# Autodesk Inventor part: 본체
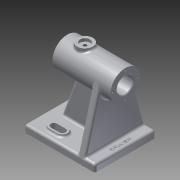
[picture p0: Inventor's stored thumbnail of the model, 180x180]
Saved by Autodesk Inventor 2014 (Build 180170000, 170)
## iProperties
Created: 2019-10
Part Number: 본체
Material: Aluminum 6061
Document SubType Name: Modeling
Designer: kh
Density: 2.71 g/cm^3
Appearance: Aluminum - Flat
Mass: 588.616 g
Surface Area: 540.304 cm^2
Volume: 217.201 cm^3
Author: kh
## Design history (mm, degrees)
sketch "Sketch1"
  geometry: L1 (-50, -43)-(50, -43); L2 (50, -43)-(50, 43); L3 (50, 43)-(-50, 43); L4 (-50, 43)-(-50, -43); L5 (-50, -43)-(50, 43); L6 (50, -43)-(-50, 43); L7 (-24, 27)-(-12, 27); L8 (-24, 31.5)-(-12, 31.5); L9 (-12, 22.5)-(-24, 22.5); L10 (-24, -27)-(-12, -27); L11 (-24, -22.5)-(-12, -22.5); L12 (-12, -31.5)-(-24, -31.5); A1 r 4.5 centre (-24, 27) between (-24, 31.5) and (-24, 22.5); A2 r 4.5 centre (-12, 27) between (-12, 22.5) and (-12, 31.5); A3 r 4.5 centre (-24, -27) between (-24, -22.5) and (-24, -31.5); A4 r 4.5 centre (-12, -27) between (-12, -31.5) and (-12, -22.5); 3 further points
  constraints: 28 end point, 8 point on circle, 8 tangent, 6 parallel, 4 centre point, 4 midpoint, 1 horizontal, 1 perpendicular
  dimensions: "d0" = 100 distance of L3.end L2.end; "d1" = 86 distance of L2.end L1.end; "d2" = 27 distance from line of L7 point (0, 0); "d3" = 12 distance of L8.start L8.end; "d4" = 26 distance from line of L4 L8.start; "d5" = 9 distance between parallel lines of L9 L8; "d6" = 12 distance of L11.start L11.end; "d7" = 9 distance between parallel lines of L12 L11; "d9" = 26 distance from line of L4 L11.start; "d80" = 27 vertical distance of point (-18, -27) point (0, 0)
extrude "Extrusion1" new body sketch "Sketch1" distance "d10" = 10; taper "d11" = 0 deg
sketch "Sketch2"
  geometry: L1 (-24, 27)-(-12, 27); L2 (-24, 20)-(-12, 20); L3 (-12, 34)-(-24, 34); L4 (-24, -27)-(-12, -27); L5 (-24, -34)-(-12, -34); L6 (-12, -20)-(-24, -20); L7 (-24, 27)-(-12, 27); L8 (-24, 22.5)-(-12, 22.5); L9 (-12, 31.5)-(-24, 31.5); L10 (-24, -27)-(-12, -27); L11 (-24, -31.5)-(-12, -31.5); L12 (-12, -22.5)-(-24, -22.5); A1 r 4.5 centre (-24, 27) between (-24, 31.5) and (-24, 22.5) reference; A2 r 4.5 centre (-12, 27) between (-12, 22.5) and (-12, 31.5) reference; A3 r 4.5 centre (-24, -27) between (-24, -22.5) and (-24, -31.5) reference; A4 r 4.5 centre (-12, -27) between (-12, -31.5) and (-12, -22.5) reference; A5 r 7 centre (-24, 27) between (-24, 34) and (-24, 20); A6 r 7 centre (-12, 27) between (-12, 20) and (-12, 34); A7 r 7 centre (-24, -27) between (-24, -20) and (-24, -34); A8 r 7 centre (-12, -27) between (-12, -34) and (-12, -20); A9 r 4.5 centre (-24, 27) between (-24, 31.5) and (-24, 22.5); A10 r 4.5 centre (-12, 27) between (-12, 22.5) and (-12, 31.5); A11 r 4.5 centre (-24, -27) between (-24, -22.5) and (-24, -31.5); A12 r 4.5 centre (-12, -27) between (-12, -31.5) and (-12, -22.5); 5 further points
  constraints: 32 end point, 16 point on circle, 16 tangent, 8 centre point, 7 equal length, 4 midpoint, 1 horizontal
  dimensions: "d12" = 14 distance between parallel lines of L2 L3; "d13" = 14 distance between parallel lines of L5 L6; "d14" = 9 distance between parallel lines of L11 L12; "d15" = 9 distance between parallel lines of L9 L8
extrude "Extrusion2" join sketch "Sketch2" distance "d16" = 3; taper "d17" = 0 deg
sketch "Sketch3"
  geometry: L1 (32, 86)-(-30, 86); L2 (-30, 86)-(-30, 100.5); L3 (-30, 100.5)-(32, 100.5); L4 (32, 100.5)-(32, 86); L5 (-30, 86)-(-50, 86); L6 (-50, 86)-(-50, 97.5); L7 (-50, 97.5)-(-30, 97.5); L8 (-30, 97.5)-(-30, 86); L9 (32, 86)-(-50, 86); L10 (-50, 86)-(-50, 107); L11 (-50, 107)-(32, 107); L12 (32, 107)-(32, 86); L13 (-50, 0)-(-50, 10) reference; L14 (50, 0)-(-50, 0) reference; 5 further points
  constraints: 24 end point, 6 parallel, 4 midpoint, 3 horizontal, 3 perpendicular, 2 vertical alignment
  dimensions: "d18" = 29 diameter of L3 L1; "d19" = 23 diameter of L7 L5; "d20" = 42 diameter of L11 L5; "d21" = 82 distance of L10.end L11.end; "d22" = 62 distance of L2.end L3.end; "d23" = 86 distance from line of L1.start L14
revolve "Revolution1" sketch "Sketch3" stored, may be unused: angle "d24" = 90 deg
workplane "Work Plane1"
sketch "Sketch4"
  geometry: L1 (-32, 21)-(-32, -21) reference; C1 r 11 at (-7, 0); 2 further points
  constraints: 1 centre point, 1 coincident, 1 horizontal alignment, 1 midpoint
  dimensions: "d26" = 22 diameter of C1; "d79" = 25 distance from line of point (-7, 0) L1
extrude "Extrusion3" join sketch "Sketch4" stored distance "d27" = 3; taper "d28" = 0 deg
hole "Hole1" diameter "d31" = 4.917; stored, may be unused: countersink angle "d35" = 90 deg, drill point angle "d37" = 118 deg; dims "d29" = 10, "d30" = 10, "d32" = 6, "d33" = 14, "d34" = 4, "d36" = 8
sketch "Sketch6" dims "d39" = 36
  geometry: C1 r 21 at (0, 0) reference; 3 further points
  constraints: 1 coincident, 1 horizontal alignment, 2 other
hole "Hole2" sketch "Sketch6" at (18, 0) diameter "d40" = 2.459; stored, may be unused: countersink angle "d44" = 90 deg, drill point angle "d46" = 118 deg; dims "d41" = 8, "d42" = 14, "d43" = 4, "d45" = 10
pattern_circular "Circular Pattern1" dims angle "d48" = 360 deg
workplane "Work Plane2"
mirror "Mirror1"
fillet "Fillet1" dims "d50" = 3
fillet "Fillet2" dims "d51" = 3
fillet "Fillet3" dims "d52" = 3
workplane "Work Plane4"
sketch "Sketch8"
  geometry: L1 (-10, 0)-(-10, 80) reference; L2 (-7, 83)-(0, 83) reference; L3 (0, 83)-(0, -3) reference; L4 (0, -3)-(-7, -3) reference; L5 (-7.783, 82.896)-(-91.48, 60.272); L6 (-7.783, -2.896)-(-91.48, 19.728); L7 (-10, 80)-(-10, 0); C1 r 11.5 at (-86, 40) reference; A1 r 3 centre (-7, 80) between (-7, 83) and (-10, 80) reference; A2 r 3 centre (-7, 0) between (-10, 0) and (-7, -3) reference; A3 r 21 centre (-86, 40) between (-91.48, 60.272) and (-91.48, 19.728) reference; A4 r 21 centre (-86, 40) between (-91.48, 19.728) and (-91.48, 60.272); A5 r 3 centre (-7, 0) between (-10, 0) and (-7.783, -2.896); A6 r 3 centre (-7, 80) between (-7.783, 82.896) and (-10, 80); 1 further point
  constraints: 10 point on circle, 8 tangent, 6 end point, 3 centre point, 3 coincident, 1 collinear
extrude "Extrusion4" join sketch "Sketch8" distance "d56" = 10; taper "d57" = 0 deg
sketch "Sketch9"
  geometry: L1 (0, 106)-(4.542, 106) reference; L2 (4.542, 106)-(4.542, 100.5) reference; L3 (4.542, 100.5)-(-30, 100.5) reference; L4 (-30, 100.5)-(-30, 97.5) reference; L5 (-30, 97.5)-(-50, 97.5) reference; L6 (-50, 97.5)-(-50, 102.77) reference; L7 (-50, 102.77)-(-40, 102.77) reference; L8 (-40, 102.77)-(-39.261, 104) reference; L9 (-39.261, 104)-(-40, 105.229) reference; L10 (-40, 105.229)-(-50, 105.229) reference; L11 (-50, 105.229)-(-50, 107) reference; L12 (-50, 107)-(-4, 107) reference; L13 (-4, 107)-(-4, 110) reference; L14 (-4, 110)-(0, 110) reference; L15 (0, 110)-(0, 106) reference; L16 (9.459, 106)-(14, 106) reference; L17 (14, 106)-(14, 110) reference; L18 (14, 110)-(18, 110) reference; L19 (18, 110)-(18, 107) reference; L20 (18, 107)-(32, 107) reference; L21 (32, 107)-(32, 105.23) reference; L22 (32, 105.23)-(22, 105.23) reference; L23 (22, 105.23)-(21.261, 104) reference; L24 (21.261, 104)-(22, 102.771) reference; L25 (22, 102.771)-(32, 102.771) reference; L26 (32, 102.771)-(32, 100.5) reference; L27 (32, 100.5)-(9.459, 100.5) reference; L28 (9.459, 100.5)-(9.459, 106) reference; L29 (-30, 71.5)-(32, 71.5) reference; L30 (32, 71.5)-(32, 69.23) reference; L31 (32, 69.23)-(22, 69.23) reference; L32 (22, 69.23)-(21.261, 68) reference; L33 (21.261, 68)-(22, 66.77) reference; L34 (22, 66.77)-(32, 66.77) reference; L35 (32, 66.77)-(32, 65) reference; L36 (32, 65)-(-25, 65) reference; L37 (-25, 65)-(-25, 10) reference; L38 (-25, 10)-(47, 10) reference; L39 (50, 7)-(50, 0) reference; L40 (50, 0)-(-50, 0) reference; L41 (-50, 0)-(-50, 7) reference; L42 (-47, 10)-(-35, 10) reference; L43 (-35, 10)-(-35, 65) reference; L44 (-35, 65)-(-50, 65) reference; L45 (-50, 65)-(-50, 66.77) reference; L46 (-50, 66.77)-(-40, 66.77) reference; L47 (-40, 66.77)-(-39.261, 68) reference; L48 (-39.261, 68)-(-40, 69.229) reference; L49 (-40, 69.229)-(-50, 69.229) reference; L50 (-50, 69.229)-(-50, 74.5) reference; L51 (-50, 74.5)-(-30, 74.5) reference; L52 (-30, 74.5)-(-30, 71.5) reference; L53 (35, 10)-(20.959, 48.576); A1 r 3 centre (47, 7) between (50, 7) and (47, 10) reference; A2 r 3 centre (-47, 7) between (-47, 10) and (-50, 7) reference; 1 further point
  constraints: 2 end point, 1 point on line
  dimensions: "d58" = 70 deg angle of L38 L53; "d59" = 15 distance from line of L53.start L39
feature "Rib1" sketch "Sketch9" dims "d60" = 1, "d61" = 10, "d62" = 0, "d63" = 0, "d64" = 1, "d65" = 1
fillet "Fillet4" dims "d66" = 3
fillet "Fillet5" dims "d67" = 3
fillet "Fillet6" dims "d68" = 3
fillet "Fillet7" dims "d69" = 3
fillet "Fillet8" dims "d70" = 3
sketch "Sketch10"
  geometry: L1 (40.598, -15.156)-(40.598, 15.156); L2 (40.598, 15.156)-(45.402, 15.156); L3 (45.402, 15.156)-(45.402, -15.156); L4 (45.402, -15.156)-(40.598, -15.156); L5 (40.598, 15.156)-(45.402, -15.156); L6 (40.598, -15.156)-(45.402, 15.156); L7 (50, -40)-(50, 40) reference; L8 (47, 43)-(-47, 43) reference; 2 further points
  constraints: 4 end point, 1 midpoint, 2 other
  dimensions: "d71" = 7 distance from line of L7 point (43, 0); "d72" = 43 distance from line of L8 point (43, 0)
emboss "Emboss1" sketch "Sketch10" dims "d0" = 100, "d1" = 86, "d2" = 27, "d3" = 12, "d4" = 26, "d5" = 9, "d6" = 12, "d7" = 9, "d9" = 26, "d73" = 0.5, "d74" = 0, "d80" = 27
chamfer "Chamfer1" distance "d75" = 1; stored, may be unused: second distance "d76" = 2, angle "d77" = 45 deg
fillet "Fillet9" dims "d78" = 3
body "Solid1"
node "Project Cut Edges1"
node "Project Cut Edges2"
other parameters: "d55" = -15
